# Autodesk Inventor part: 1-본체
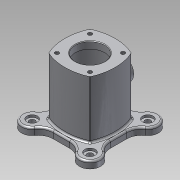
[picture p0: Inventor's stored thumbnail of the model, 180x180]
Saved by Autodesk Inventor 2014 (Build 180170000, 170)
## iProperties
Created: 2016-05
Part Number: 1-본체
Material: 알루미늄 6061
Document SubType Name: Modeling
Designer: S.Y.PARK
Density: 2.71 g/cm^3
Appearance: 알루미늄 - 평지
Mass: 1105.56 g
Surface Area: 871.882 cm^2
Volume: 407.954 cm^3
Author: S.Y.PARK
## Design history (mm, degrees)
sketch "스케치1"
  geometry: L1 (-35.355, -35.355)-(35.355, -35.355); L2 (35.355, -35.355)-(35.355, 35.355); L3 (35.355, 35.355)-(-35.355, 35.355); L4 (-35.355, 35.355)-(-35.355, -35.355); L5 (-35.355, -35.355)-(35.355, 35.355); L6 (35.355, -35.355)-(-35.355, 35.355); A1 r 85.579 centre (0, 42.579) between (-35.355, -35.355) and (35.355, -35.355); A2 r 85.579 centre (0, -42.579) between (35.355, 35.355) and (-35.355, 35.355); A3 r 85.579 centre (42.579, 0) between (-35.355, 35.355) and (-35.355, -35.355); A4 r 85.579 centre (-42.579, 0) between (35.355, -35.355) and (35.355, 35.355); 4 further points
  constraints: 12 end point, 9 point on circle, 4 centre point, 2 equal radius, 2 midpoint, 2 parallel, 2 perpendicular, 1 coincident, 1 horizontal, 1 vertical alignment
  dimensions: "d2" = 100 distance of L1.start L2.end; "d3" = 86 dimension on A2 A1; "d4" = 43 distance of point (0, 0) point (0, -43)
extrude "돌출1" new body sketch "스케치1" distance "d5" = 98; taper "d6" = 0 deg
sketch "스케치2"
  geometry: L1 (49, -49)-(-49, -49); L2 (-49, -49)-(-49, 49); L3 (-49, 49)-(49, 49); L4 (49, 49)-(49, -49); 3 further points
  constraints: 8 end point, 2 midpoint, 2 parallel, 1 horizontal, 1 horizontal alignment, 1 perpendicular, 1 vertical alignment
  dimensions: "d7" = 98 distance of L1.start L1.end; "d8" = 98 distance of L1.end L2.end
extrude "돌출2" join sketch "스케치2" distance "d9" = 12; taper "d10" = 0 deg
sketch "스케치3"
  geometry: L1 (0, 0)-(49.497, -49.497); L2 (0, 0)-(29.49, 0); L3 (0, 0)-(0, -21.208); C1 r 18 at (49.497, -49.497); C2 r 18 at (49.497, 49.497); C3 r 18 at (-49.497, -49.497); C4 r 18 at (-49.497, 49.497); 1 further point
  constraints: 6 end point, 4 centre point, 3 symmetric about line, 2 coincident, 1 horizontal, 1 perpendicular, 3 other
  dimensions: "d12" = 45 deg angle of L2 L1; "d13" = 70 distance of L1.start L1.end; "d14" = 29.49011 distance of L1.start L2.end; "d16" = 18 radius of C1; "d17" = 21.20826 distance of L1.start L3.end
extrude "돌출3" join sketch "스케치3" distance "d18" = 12; taper "d19" = 0 deg
fillet "모깎기1" dims "d20" = 25
node "작업 평면1"
sketch "스케치4"
  geometry: L1 (14.162, -12)-(-14.162, -12) reference; C1 r 20 at (0, 49); 1 further point
  constraints: 1 centre point, 1 vertical alignment
  dimensions: "d22" = 61 distance from line of L1 C1.centre; "d23" = 40 diameter of C1
extrude "돌출4" join sketch "스케치4" stored distance "d24" = 12; taper "d25" = 10 deg
hole "구멍1" diameter "d28" = 25; stored, may be unused: countersink angle "d32" = 90 deg, drill point angle "d34" = 0 deg; dims "d26" = 10, "d27" = 10, "d29" = 6, "d30" = 30, "d31" = 8, "d33" = 8
sketch "스케치5"
  geometry: 2 further points
  constraints: 1 coincident
hole "구멍2" sketch "스케치5" at (0, 0) diameter "d35" = 50; stored, may be unused: countersink angle "d39" = 90 deg, drill point angle "d41" = 0 deg; dims "d36" = 6, "d37" = 30, "d38" = 8, "d40" = 12
hole "구멍3" diameter "d44" = 70; stored, may be unused: countersink angle "d48" = 90 deg, drill point angle "d50" = 0 deg; dims "d42" = 10, "d43" = 10, "d45" = 6, "d46" = 30, "d47" = 8, "d49" = 86
hole "구멍4" diameter "d53" = 50; stored, may be unused: countersink angle "d57" = 90 deg, drill point angle "d59" = 0 deg; dims "d51" = 10, "d52" = 10, "d54" = 6, "d55" = 30, "d56" = 8, "d58" = 12
sketch "스케치6"
  geometry: L1 (0, 0)-(-13.472, 0); L2 (0, 0)-(-28.284, 28.284)
  constraints: 4 end point, 1 horizontal
  dimensions: "d60" = 40 distance of L1.start L2.end; "d61" = 45 deg angle of L2 L1; "d62" = 13.47211 distance of L1.start L1.end
hole "구멍5" sketch "스케치6" at (-28.284, 28.284) diameter "d63" = 6.647; stored, may be unused: countersink angle "d67" = 90 deg, drill point angle "d69" = 118 deg; dims "d64" = 7, "d65" = 30, "d66" = 8, "d68" = 10
node "작업 평면2"
hole "구멍6" diameter "d75" = 10; stored, may be unused: countersink angle "d79" = 90 deg, drill point angle "d81" = 0 deg; dims "d73" = 10, "d74" = 10, "d76" = 7, "d77" = 18, "d78" = 4, "d80" = 10
fillet "모깎기2" dims "d85" = 3
chamfer "모따기1" distance "d86" = 1; stored, may be unused: second distance "d87" = 2, angle "d88" = 45 deg
fillet "모깎기3" dims "d89" = 3
fillet "모깎기4" dims "d90" = 3
chamfer "모따기2" distance "d91" = 1; stored, may be unused: second distance "d92" = 2, angle "d93" = 45 deg
fillet "모깎기5" dims "d94" = 3
fillet "모깎기6" dims "d95" = 3
fillet "모깎기7" dims "d96" = 3
node "작업 평면3"
sketch "스케치7"
  geometry: L1 (34.285, 98)-(-34.285, 98) reference; 2 further points
  constraints: 1 other
  dimensions: "d97" = 29 horizontal distance of point (0, 0) point (-29, 49); "d98" = 49 distance from line of L1 point (-29, 49)
feature "엠보싱1" sketch "스케치7" dims "d2" = 100, "d3" = 86, "d4" = 43, "d99" = 0.5, "d100" = 0
node "솔리드1"
pattern_circular "원형 패턴1" dims angle "d71" = 360 deg
mirror "대칭1"
pattern_circular "원형 패턴2" dims angle "d83" = 360 deg
other parameters: "d21" = 55
